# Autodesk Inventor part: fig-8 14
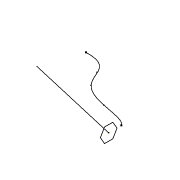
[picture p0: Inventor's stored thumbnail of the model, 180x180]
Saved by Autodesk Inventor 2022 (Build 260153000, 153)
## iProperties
Created: 2004-05
Part Number: fig-8 14
Document SubType Name: Modeling
Designer: CADCIM Technologies
Manufacturer: Standard
Standards Organization: Custom
Density: 1 g/cm^3
Material: Generic
Appearance: Default
Author: CADCIM Technologies
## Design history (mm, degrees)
workplane "Work Plane2"
sketch "Sketch7"
  geometry: L1 (-42.583, 6.068)-(-42.583, 0.37) reference; 5 further points
  constraints: 1 point on line, 5 other
sketch "Sketch8"
  geometry: L1 (-42.583, 3.219)-(-107.269, 18.236); L2 (-42.583, 6.068)-(-42.583, 0.37) reference
  constraints: 2 end point, 1 midpoint
sketch "Sketch2"
  geometry: L1 (-5.697, 0)-(-2.849, 4.934); L2 (-2.849, 4.934)-(2.849, 4.934); L3 (2.849, 4.934)-(5.697, 0); L4 (5.697, 0)-(2.849, -4.934); L5 (2.849, -4.934)-(-2.849, -4.934); L6 (-2.849, -4.934)-(-5.697, 0); 2 further points
  constraints: 12 end point, 1 coincident, 12 other
